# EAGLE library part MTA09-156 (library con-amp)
AMP connector
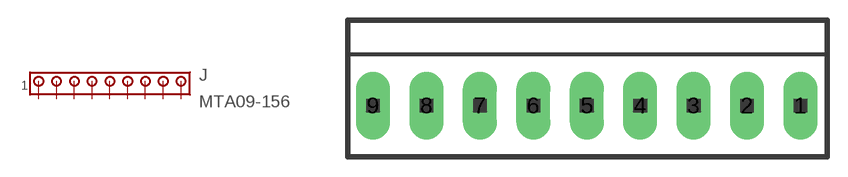
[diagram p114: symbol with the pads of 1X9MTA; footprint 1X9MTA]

Designator prefix J

## MTA09-156 (OC_FARNELL: unknown; OC_NEWARK: unknown)  [1X9MTA]
1  1  pas
2  2  pas
3  3  pas
4  4  pas
5  5  pas
6  6  pas
7  7  pas
8  8  pas
9  9  pas

## Footprint 1X9MTA (pad centres in mm)
AMP MTA connector
drill 1.676 long: 1 15.85,0; 2 11.887,0; 3 7.925,0; 4 3.962,0; 5 0,0; 6 -3.962,0; 7 -7.925,0; 8 -11.887,0; 9 -15.85,0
